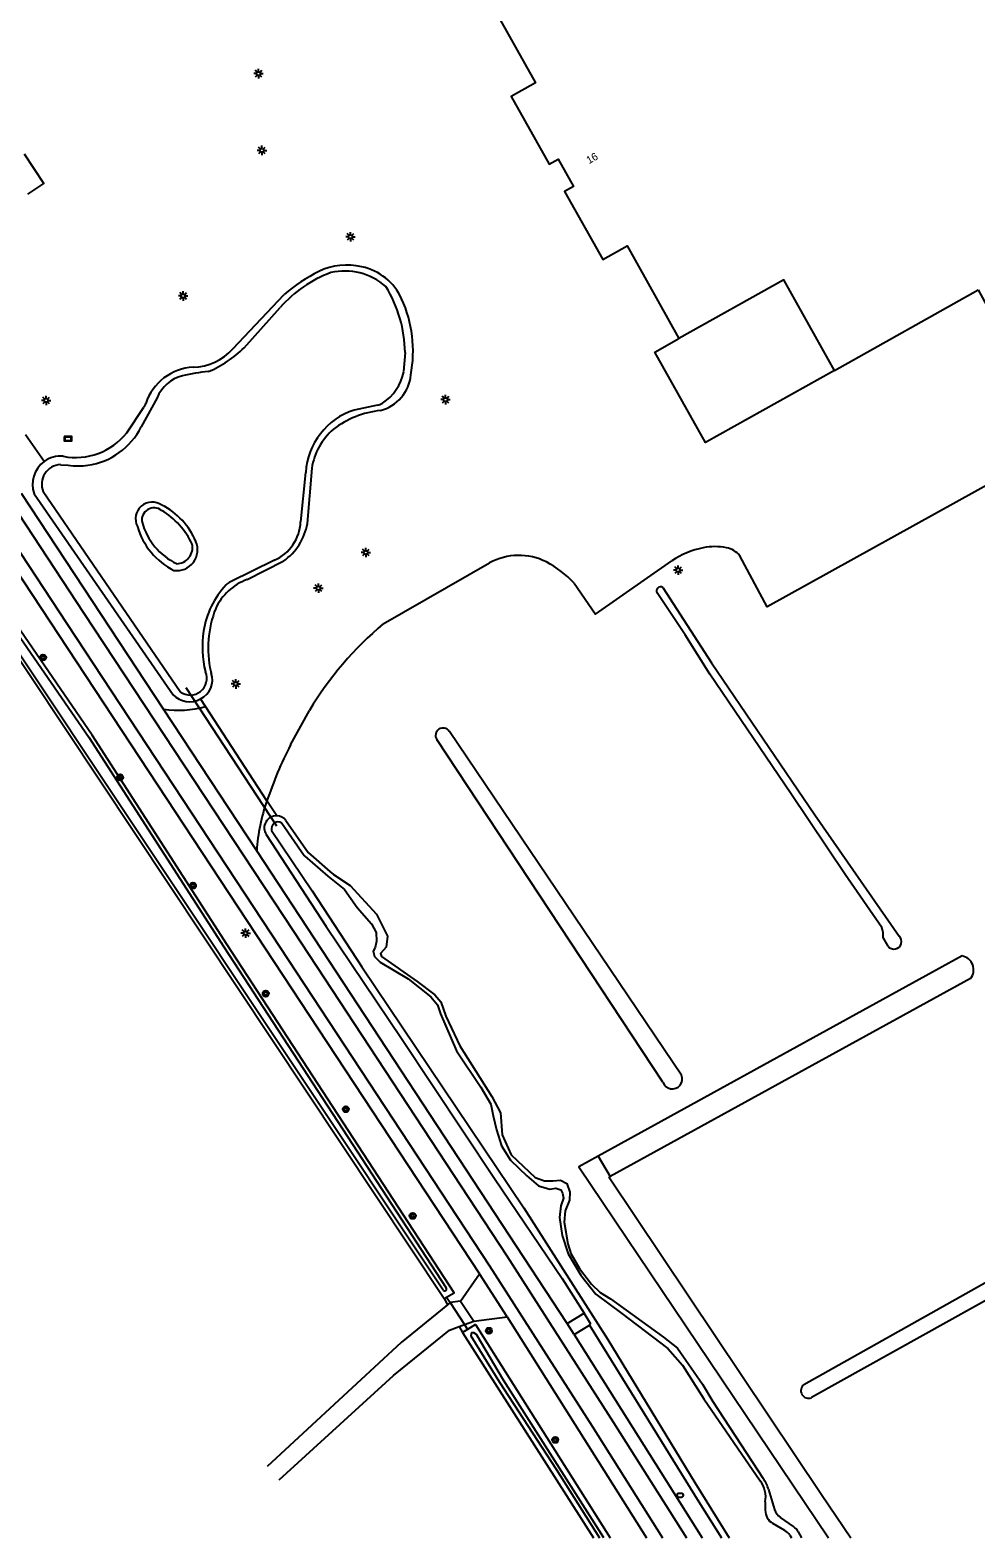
# Model space of a CAD drawing. Extents: x 137000 to 140001, y 403500 to 406000.
# Drawn here: x 139724.5 to 139849.2, y 403500 to 403698.8 of the extents above; entities that cross this region are included whole.
import ezdxf

# ---------------------------------------------------------------- set-up
doc = ezdxf.new("R2010")
doc.units = 0
for name, color, linetype in [('gg-anno-huisnummerreeks BGT', 7, 'Continuous'), ('gg-bbg-hoofdgebouw', 7, 'Continuous'), ('gg-bbg-luifel en loopbrug', 7, 'Continuous'), ('gg-knt-bronhoudergrens', 7, 'Continuous'), ('gg-knt-onverhard', 7, 'Continuous'), ('gg-knt-verharding', 7, 'Continuous'), ('gg-knt-verharding nz', 7, 'Continuous'), ('gg-kntw-bovenkant insteek waterloop', 7, 'Continuous'), ('gg-kntw-waterlijn', 7, 'Continuous'), ('gg-kwrk-duiker nz buis', 7, 'Continuous'), ('gt-grn-groengrens', 7, 'Continuous'), ('gt-grn-groengrens NZ', 7, 'Continuous'), ('gt-grn-vlakafsluiter', 7, 'Continuous'), ('gt-symb-boom', 7, 'Continuous'), ('gt-symb-brandkraan', 7, 'Continuous'), ('gt-symb-informatiebord', 7, 'Continuous'), ('gt-symb-lichtmast', 7, 'Continuous')]:
    doc.layers.add(name, color=color, linetype=linetype)

# ---------------------------------------------------------------- blocks, each defined once
blk = doc.blocks.new('gt0-LMAST')
at = {"layer": 'gt-symb-lichtmast'}
for p, q in [((-0.18, 0.17), (-0.45, 0.44)), ((-0.01, 0.25), (-0.01, 0.62)), ((0.17, 0.17), (0.44, 0.44)), ((-0.26, 0), (-0.63, 0)), ((-0.18, -0.18), (-0.45, -0.45)), ((-0.01, -0.25), (-0.01, -0.63)), ((0.44, -0.45), (0.17, -0.18)), ((0.24, 0), (0.62, 0))]:
    blk.add_line(p, q, dxfattribs=at)
blk.add_circle((-0.01, 0), 0.25, dxfattribs=at)
blk = doc.blocks.new('gt0-IBORD')
at = {"layer": 'gt-symb-informatiebord'}
blk.add_lwpolyline([(-0.5, 0.29), (-0.5, -0.29), (0.5, -0.29), (0.5, 0.29), (-0.5, 0.29)], dxfattribs=at)
blk.add_lwpolyline([(-0.42, -0.21), (0.42, -0.21), (0.42, 0.21), (-0.42, 0.21)], close=True, dxfattribs=at)
blk = doc.blocks.new('gt0-BOOM')
at = {"layer": 'gt-symb-boom'}
for radius in [0.4, 0.2]:
    blk.add_circle((0, 0), radius, dxfattribs=at)
blk = doc.blocks.new('gt0-BR')
at = {"layer": 'gt-symb-brandkraan'}
for centre, radius, start, end in [((-0.24, 0), 0.206, 107.5669, 252.4331), ((0.6, -2.66), 3, 106.892, 107.5669), ((0, -0.69), 0.938, 73.108, 106.892), ((-0.6, -2.66), 3, 72.4331, 73.108), ((0.24, 0), 0.206, 287.567, 72.4331), ((0.6, 2.66), 3, 252.4331, 253.108), ((0, 0.69), 0.938, 253.108, 286.8921), ((-0.6, 2.66), 3, 286.8921, 287.567)]:
    blk.add_arc(centre, radius, start, end, dxfattribs=at)

msp = doc.modelspace()

# ---------------------------------------------------------------- linework, layer by layer
at = {"layer": 'gg-bbg-hoofdgebouw'}
msp.add_line((139830.55, 403653.9), (139849.47, 403664.54), dxfattribs=at)
for points in [[(139933.95, 403789.41), (139907.29, 403836.88), (139856.67, 403808.46), (139858.9, 403804.49), (139792.07, 403766.97), (139793.17, 403765.01), (139757.34, 403744.95), (139767.31, 403727.14), (139770.38, 403728.86), (139791.13, 403691.82), (139787.93, 403690.03), (139792.93, 403681.12), (139794.11, 403681.78), (139796.15, 403678.16), (139794.97, 403677.5), (139799.99, 403668.55), (139803.2, 403670.36), (139810.03, 403658.13)], [(139830.55, 403653.9), (139823.87, 403665.86), (139810.03, 403658.13)]]:
    msp.add_lwpolyline(points, dxfattribs=at)
at = {"layer": 'gg-bbg-luifel en loopbrug'}
for points in [[(139724.24, 403677.18), (139726.32, 403678.55), (139723.78, 403682.42)], [(139830.55, 403653.9), (139813.55, 403644.41), (139806.85, 403656.34), (139810.03, 403658.13)]]:
    msp.add_lwpolyline(points, dxfattribs=at)
at = {"layer": 'gg-knt-bronhoudergrens'}
for p, q in [((139800.79, 403547.58), (139828.84, 403505.71)), ((139828.84, 403505.71), (139832.68, 403500))]:
    msp.add_line(p, q, dxfattribs=at)
msp.add_lwpolyline([(139799.4, 403550.33), (139796.83, 403548.92), (139829.77, 403500)], dxfattribs=at)
at = {"layer": 'gg-knt-onverhard'}
for p, q in [((139779.89, 403531.01), (139779.54, 403530.72)), ((139781.24, 403531.21), (139779.89, 403531.01)), ((139779.8, 403527.37), (139781.07, 403527.87)), ((139781.07, 403527.87), (139781.76, 403528.14)), ((139781.76, 403528.14), (139783.01, 403528.55))]:
    msp.add_line(p, q, dxfattribs=at)
for points in [[(139779.54, 403530.72), (139773.42, 403525.76), (139755.77, 403509.42)], [(139757.35, 403507.65), (139772.43, 403521.42), (139779.8, 403527.37)]]:
    msp.add_lwpolyline(points, dxfattribs=at)
at = {"layer": 'gg-knt-verharding'}
for p, q in [((139715.26, 403638.85), (139783.75, 403534.79)), ((139742.1, 403609.27), (139723.38, 403637.68)), ((139771.05, 403620.49), (139785.08, 403628.55)), ((139755.75, 403597.18), (139747.65, 403609.61)), ((139758.83, 403604.54), (139761.37, 403609.1)), ((139795.31, 403528.24), (139754.4, 403590.59)), ((139781.24, 403531.21), (139783.75, 403534.79)), ((139787.4, 403529.15), (139783.75, 403534.79)), ((139781.24, 403531.21), (139783.01, 403528.55)), ((139781.76, 403528.14), (139782.18, 403527.49)), ((139783.01, 403528.55), (139787.4, 403529.15)), ((139787.4, 403529.15), (139805.77, 403500)), ((139795.31, 403528.24), (139797.53, 403529.63)), ((139796.24, 403526.82), (139795.31, 403528.24)), ((139796.24, 403526.82), (139798.23, 403528.06)), ((139798.44, 403528.19), (139797.53, 403529.63)), ((139798.23, 403528.06), (139798.44, 403528.19)), ((139796.24, 403526.82), (139813.1, 403500))]:
    msp.add_line(p, q, dxfattribs=at)
for points in [[(139849.47, 403664.54), (139860.46, 403644.25), (139821.68, 403622.77), (139818.07, 403629.47)], [(139796.22, 403625.86), (139799.06, 403621.8), (139809.09, 403628.81)]]:
    msp.add_lwpolyline(points, dxfattribs=at)
for centre, radius, start, end in [((139788.94, 403621.51), 8.03, 63.1111, 118.7394), ((139815.42, 403619.5), 11.25, 101.1241, 124.2388), ((139814.77, 403622.3), 8.39, 79.5534, 100.4466), ((139815.74, 403627.62), 2.98, 38.4886, 79.2807), ((139786.67, 403617.23), 12.87, 42.1357, 62.7241), ((139799.28, 403586.69), 44.04, 129.8645, 149.4084), ((139744.09, 403622.19), 13.08, 261.26, 285.7962), ((139806.12, 403580.4), 53.09, 152.9573, 161.5822), ((139778.2, 403589.16), 23.84, 160.351, 176.561)]:
    msp.add_arc(centre, radius, start, end, dxfattribs=at)
at = {"layer": 'gg-knt-verharding nz'}
msp.add_line((139754.4, 403590.59), (139742.1, 403609.27), dxfattribs=at)
for points in [[(139568.03, 403889.64), (139571.85, 403881.88), (139575.08, 403875.25), (139577.18, 403870.82), (139579.94, 403865.74), (139593.13, 403843.22), (139606.51, 403820.75), (139634.96, 403773.42), (139647.99, 403751.99), (139661.28, 403730.67), (139675.19, 403708.59), (139689.23, 403686.58), (139702.91, 403665.56), (139731.61, 403621.93), (139759.26, 403580.01), (139787.35, 403537.2), (139801.42, 403515.21), (139811.03, 403500)], [(139562.49, 403886.42), (139566.67, 403880.85), (139571.89, 403873.33), (139574.49, 403869.35), (139577.61, 403864.3), (139590.95, 403841.87), (139604.28, 403819.39), (139617.16, 403797.87), (139632.68, 403772.16), (139646.25, 403749.84), (139659.52, 403728.52), (139672.94, 403707.28), (139686.99, 403685.26), (139701.23, 403663.38), (139729.36, 403620.55), (139757.47, 403577.82), (139785.09, 403535.88), (139798.6, 403514.72), (139807.89, 403500)]]:
    msp.add_lwpolyline(points, dxfattribs=at)
at = {"layer": 'gg-kntw-bovenkant insteek waterloop'}
for p, q in [((139751.23, 403656.77), (139758.03, 403663.93)), ((139737.27, 403645.71), (139739.54, 403649.09)), ((139761.64, 403641.03), (139761.06, 403633.73)), ((139725.06, 403637.66), (139743.38, 403611.16)), ((139709.22, 403636.65), (139779.1, 403531.54)), ((139753.15, 403626.34), (139757.9, 403628.77)), ((139748.34, 403614.22), (139748.4, 403614)), ((139807.93, 403560.09), (139778.13, 403605.24)), ((139810.39, 403560.99), (139779.78, 403606.33)), ((139837.6, 403578), (139836.94, 403579.16)), ((139847.35, 403576.72), (139799.4, 403550.33)), ((139848.45, 403573.73), (139800.96, 403547.65)), ((139799.4, 403550.33), (139800.96, 403547.65)), ((139779.1, 403531.54), (139779.42, 403531.72)), ((139783.23, 403528.15), (139782.18, 403527.49)), ((139783.23, 403528.15), (139800.96, 403500)), ((139782.18, 403527.49), (139781.51, 403527.06)), ((139781.51, 403527.06), (139798.77, 403500)), ((139821.85, 403506.37), (139822.63, 403503.75)), ((139825.14, 403501.48), (139823.41, 403502.68)), ((139825.77, 403500.79), (139826.19, 403500))]:
    msp.add_line(p, q, dxfattribs=at)
for points in [[(139779.42, 403531.72), (139780.4, 403532.31), (139750.48, 403578.19), (139732.69, 403605.83), (139712.24, 403635.61), (139711.08, 403637.33)], [(139807.9, 403625.32), (139814.34, 403615.38), (139827.94, 403595.34), (139839.07, 403579.34)], [(139836.79, 403580.48), (139831.94, 403587.44), (139824.77, 403598.12), (139814.11, 403613.89), (139810.85, 403619.04), (139807.15, 403624.6)], [(139758.24, 403594.59), (139761.17, 403590.35), (139764.02, 403587.87), (139764.51, 403587.47), (139766.71, 403585.99), (139770.18, 403582.22), (139771.64, 403579.34), (139771.47, 403577.88), (139770.73, 403577.03), (139770.82, 403576.67), (139775.55, 403573.37), (139777.88, 403571.61), (139778.68, 403570.66), (139779.31, 403568.79), (139781.16, 403564.85), (139785.36, 403558.18), (139786.53, 403556.02), (139786.74, 403553.15), (139787.93, 403550.51), (139791.08, 403547.52), (139792.3, 403547.05), (139793.42, 403547.07), (139794.44, 403547.17), (139795.27, 403546.73), (139795.67, 403545.56), (139795.63, 403544.53), (139795.04, 403543.1), (139794.91, 403541.64), (139795.4, 403538.78), (139795.78, 403537.51), (139796.92, 403535.53), (139798.52, 403533.43), (139799.66, 403532.36), (139801.03, 403531.53), (139808.02, 403526.45), (139809.83, 403524.99), (139813.16, 403520.25), (139814.52, 403517.97), (139821.15, 403507.82)], [(139755.66, 403592.72), (139763.54, 403580.59), (139773.48, 403565.84), (139785.73, 403547.39), (139794.67, 403534.2), (139797.53, 403529.63)], [(139826.51, 403520.21), (139865.97, 403542.4), (139867.28, 403540.66), (139827.51, 403518.49)], [(139798.23, 403528.06), (139812.68, 403504.77), (139815.63, 403500)]]:
    msp.add_lwpolyline(points, dxfattribs=at)
for centre, radius, start, end in [((139773.79, 403645.28), 24.42, 117.311, 130.191), ((139766.26, 403659.31), 8.5, 76.5584, 115.5916), ((139766.78, 403660.36), 7.36, 24.1556, 78.5913), ((139758.56, 403656.49), 16.44, 348.9198, 24.7441), ((139745.85, 403661.55), 7.2, 271.4925, 318.3514), ((139746.44, 403647.34), 7.03, 93.2871, 161.4965), ((139769.42, 403653.78), 5.3, 283.9177, 355.1495), ((139737.9, 403650.19), 1.98, 326.0104, 341.6228), ((139772, 403636.36), 12.34, 96.0918, 127.4152), ((139730.55, 403650.96), 8.52, 258.7751, 321.9901), ((139770.32, 403639.57), 8.8, 131.3696, 170.4284), ((139728.56, 403638.9), 3.71, 125.9718, 199.4986), ((139728.56, 403638.91), 3.71, 84.8036, 126.0261), ((139740.87, 403634.2), 1.61, 52.0573, 190.7061), ((139736.25, 403626.34), 10.72, 25.8948, 58.402), ((139747.51, 403636.12), 8.51, 195.1101, 244.4122), ((139753.56, 403635.03), 7.62, 304.7937, 350.1637), ((139743.81, 403630.56), 2.12, 270.5963, 12.3881), ((139755.57, 403619.53), 7.23, 109.5908, 155.4326), ((139807.64, 403624.84), 0.547, 61.9075, 205.439), ((139762.38, 403617.3), 14.38, 158.6546, 192.3603), ((139745.79, 403613.11), 2.76, 295.8117, 18.9318), ((139745.53, 403613.19), 2.95, 223.2536, 299.5405), ((139778.95, 403605.78), 0.989, 33.5537, 213.152), ((139756.99, 403593.6), 1.6, 88.1579, 213.3952), ((139756.99, 403593.59), 1.6, 38.6256, 88.0911), ((139834.05, 403579.51), 2.91, 353.0488, 19.4792), ((139838.38, 403578.62), 0.996, 218.5745, 46), ((139847.01, 403574.9), 1.86, 321.0974, 79.3665), ((139809.17, 403560.51), 1.31, 199.0563, 21.4366), ((139800.36, 403548.88), 1.37, 288.2521, 296.0383), ((139827.12, 403519.41), 1.01, 127.5278, 292.981), ((139817.97, 403505.39), 4, 14.2198, 37.4118), ((139824.54, 403504.33), 2, 196.6911, 235.3891), ((139824, 403499.83), 2.01, 28.3012, 55.2911)]:
    msp.add_arc(centre, radius, start, end, dxfattribs=at)
at = {"layer": 'gg-kntw-waterlijn'}
for p, q in [((139752.76, 403656.9), (139757.49, 403662.23)), ((139773.95, 403656.29), (139773.76, 403653.76)), ((139741.26, 403650.3), (139739.16, 403646.47)), ((139770.3, 403649.35), (139767.24, 403648.7)), ((139728.54, 403641.49), (139729.55, 403641.44)), ((139760.19, 403633.96), (139760.86, 403640.47)), ((139744.31, 403611.54), (139726.26, 403637.91)), ((139778.95, 403532.67), (139710.23, 403635.83)), ((139756.72, 403628.9), (139750.93, 403626.06)), ((139821.41, 403504.73), (139821.41, 403503.63)), ((139823.99, 403500.99), (139822.41, 403501.9)), ((139824.66, 403500.35), (139824.89, 403500))]:
    msp.add_line(p, q, dxfattribs=at)
for points in [[(139710.99, 403636.35), (139711.96, 403634.96), (139732.28, 403605.56), (139750.06, 403577.92), (139779.37, 403532.97)], [(139756.36, 403593.28), (139761.72, 403585.3), (139768.23, 403575.29), (139789.61, 403543.51), (139800.68, 403526.14), (139812.15, 403507.29), (139816.66, 403500)], [(139757.71, 403594.23), (139760.63, 403589.98), (139760.74, 403589.86), (139763.76, 403587.24), (139765.96, 403585.47), (139767.65, 403583.1), (139769.53, 403580.95), (139770.12, 403579.83), (139770.16, 403578.68), (139769.99, 403577.83), (139769.76, 403577.35), (139769.92, 403576.65), (139770.68, 403575.91), (139774.34, 403573.69), (139777.34, 403571.34), (139778.23, 403570.29), (139778.61, 403569.08), (139780.73, 403564.21), (139783.94, 403559.44), (139785.27, 403557.19), (139785.56, 403555.62), (139786.01, 403553.81), (139786.67, 403551.7), (139787.84, 403549.78), (139789.99, 403547.72), (139791.55, 403546.41), (139793.04, 403545.98), (139793.82, 403546.11), (139794.49, 403545.9), (139794.68, 403545.45), (139794.81, 403544.79), (139794.49, 403543.79), (139794.3, 403542.24), (139794.66, 403539.86), (139795.45, 403537.45), (139797.09, 403534.62), (139799.09, 403532.14), (139802.51, 403529.58), (139808.59, 403524.97), (139810.49, 403522.76), (139813.34, 403518.32), (139820.75, 403507.51)], [(139800.15, 403500), (139786.93, 403520.8), (139783.36, 403526.82), (139783.01, 403527.03), (139782.68, 403527.02), (139782.63, 403526.65), (139786.39, 403520.52), (139793.85, 403509.07), (139799.58, 403500)]]:
    msp.add_lwpolyline(points, dxfattribs=at)
for centre, radius, start, end in [((139770.14, 403651), 16.91, 110.7106, 138.4049), ((139766, 403658.81), 8.22, 48.857, 102.9292), ((139756.46, 403655.91), 17.5, 1.2225, 31.3045), ((139741.38, 403668.88), 16.52, 293.7946, 313.5294), ((139745.93, 403648.33), 5.07, 105.1127, 157.1235), ((139749.77, 403631.66), 22.17, 94.4686, 103.4646), ((139767.61, 403654.9), 6.26, 302.3613, 349.4642), ((139769.88, 403651.31), 2.01, 282.0614, 302.4095), ((139770.11, 403639.89), 9.27, 108.0555, 176.3993), ((139730.77, 403650.73), 9.42, 278.4784, 333.075), ((139728.64, 403638.92), 2.58, 92.2499, 202.8409), ((139730.93, 403649.68), 8.35, 260.4634, 278.4386), ((139740.63, 403634.36), 2.2, 55.0514, 207.038), ((139737.57, 403627.62), 9.58, 22.9769, 63.1843), ((139747.66, 403635.92), 9.35, 195.8851, 243.5261), ((139754.39, 403634.21), 5.8, 293.6384, 357.5272), ((139743.87, 403630.27), 2.74, 262.0935, 23.4147), ((139758.75, 403617.77), 11.5, 136.8627, 171.1339), ((139751.81, 403624.28), 1.99, 116.1049, 137), ((139760.93, 403617.52), 13.7, 171.5107, 194.0549), ((139745.62, 403613.32), 2.2, 233.5824, 23.4261), ((139757.2, 403593.51), 0.878, 54.9156, 195.2729), ((139779.16, 403532.82), 0.258, 214.7435, 34.9134), ((139817.96, 403505.38), 3.51, 349.3328, 37.4763), ((139823.41, 403503.63), 2, 180.0073, 239.9235), ((139822.97, 403499.24), 2.01, 33.3005, 59.8526)]:
    msp.add_arc(centre, radius, start, end, dxfattribs=at)
at = {"layer": 'gg-kwrk-duiker nz buis'}
msp.add_line((139757.04, 403593.83), (139745.09, 403612.06), dxfattribs=at)
at = {"layer": 'gt-grn-groengrens'}
for p, q in [((139726.38, 403641.91), (139723.92, 403645.43)), ((139747.65, 403609.61), (139746.99, 403610.62)), ((139757.04, 403595.19), (139755.75, 403597.18)), ((139779.1, 403531.54), (139779.54, 403530.72)), ((139781.07, 403527.87), (139781.51, 403527.06))]:
    msp.add_line(p, q, dxfattribs=at)
at = {"layer": 'gt-grn-groengrens NZ'}
msp.add_line((139779.42, 403531.72), (139779.89, 403531.01), dxfattribs=at)
at = {"layer": 'gt-grn-vlakafsluiter'}
msp.add_line((139779.89, 403531.01), (139781.76, 403528.14), dxfattribs=at)

# ---------------------------------------------------------------- block references
at = {"layer": 'gt-symb-boom'}
for p in [(139726.23, 403616.07), (139736.38, 403600.27), (139745.99, 403586), (139755.58, 403571.75), (139766.14, 403556.51), (139774.95, 403542.45), (139784.99, 403527.3), (139793.73, 403512.91)]:
    msp.add_blockref('gt0-BOOM', p, dxfattribs=at)
at = {"layer": 'gt-symb-brandkraan'}
msp.add_blockref('gt0-BR', (139810.19, 403505.62), dxfattribs=at)
at = {"layer": 'gt-symb-informatiebord'}
msp.add_blockref('gt0-IBORD', (139729.52, 403644.91), dxfattribs=at)
at = {"layer": 'gt-symb-lichtmast'}
for p in [(139754.63, 403693.05), (139755.09, 403682.94), (139766.75, 403671.55), (139744.7, 403663.74), (139726.65, 403649.97), (139779.29, 403650.07), (139768.78, 403629.91), (139809.93, 403627.6), (139762.53, 403625.22), (139751.64, 403612.59), (139752.94, 403579.73)]:
    msp.add_blockref('gt0-LMAST', p, dxfattribs=at)

# ---------------------------------------------------------------- texts
at = {"layer": 'gg-anno-huisnummerreeks BGT'}
msp.add_text('16', height=1, rotation=29.3, dxfattribs=at).set_placement((139798.18, 403681.11))

doc.saveas('drawing.dxf')
